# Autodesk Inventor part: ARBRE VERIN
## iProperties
Created: 2004-11
Part Number: ARBRE VERIN
Document SubType Name: Modeling
Designer: Bruno
Manufacturer: Standard
Standards Organization: Custom
Author: Bruno
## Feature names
1. Base1
